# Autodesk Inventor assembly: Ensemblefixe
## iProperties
Shininess: 64.0
Length Units: 11269
Angle Units: 11279
Time Units: 11290
Mass Units: 11283
Length Display Precision: 3
Angle Display Precision: 2
Compacted: True
Created: 2006-01
Part Number: Ensemblefixe
Document SubType Name: Assembly
Designer: riri
Density: 0.0
Volumn: 0.0
Area: 0.0
PropertySet Name: Model Information
Control State: 0
Master: False
Checked Out: False
Author: riri
